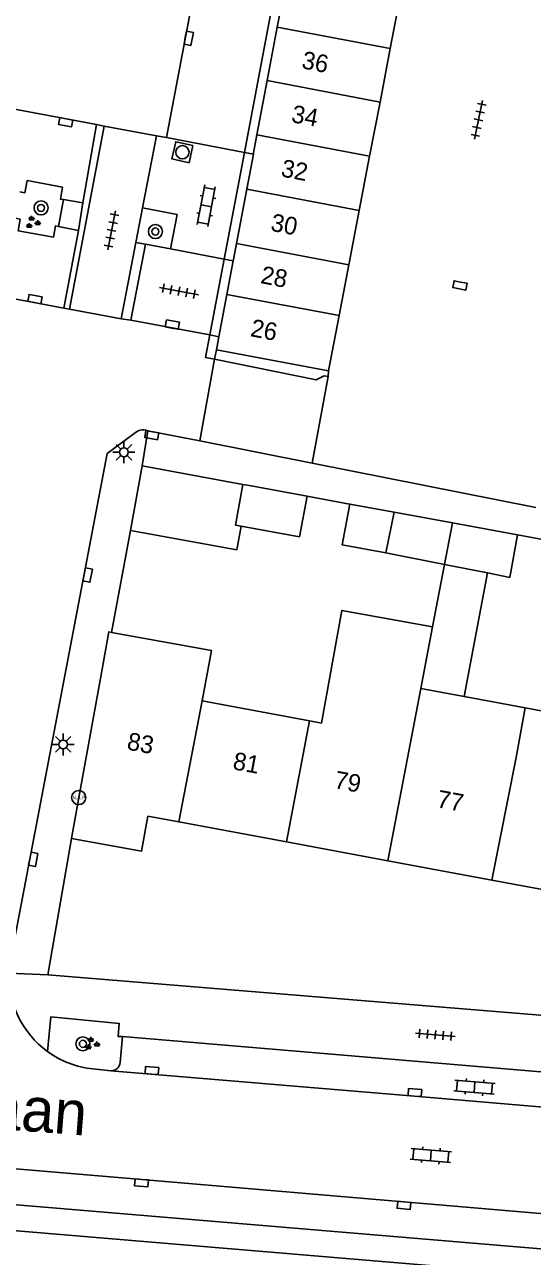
# Model space of a CAD drawing. Extents: x 131000 to 133014, y 396499 to 399001.
# Drawn here: x 131372.8 to 131401.6, y 397176.8 to 397246.7 of the extents above; entities that cross this region are included whole.
import ezdxf

# ---------------------------------------------------------------- set-up
doc = ezdxf.new("R2010")
doc.units = 0
for name, color, linetype in [('gg-afsc-erfafscheiding', 7, 'Continuous'), ('gg-afsc-muur', 7, 'Continuous'), ('gg-anno-huisnummerreeks BGT', 7, 'Continuous'), ('gg-anno-openbare ruimte label', 7, 'Continuous'), ('gg-bbg-bijgebouw', 7, 'Continuous'), ('gg-bbg-gedigitaliseerde bebouwing', 7, 'Continuous'), ('gg-bbg-gedigitaliseerde bijgebouw', 7, 'Continuous'), ('gg-bbg-hoofdgebouw', 7, 'Continuous'), ('gg-bbg-luifel en loopbrug', 7, 'Continuous'), ('gg-bbg-tussenscheiding', 7, 'Continuous'), ('gg-knt-verharding', 7, 'Continuous'), ('gg-knt-verharding nz', 7, 'Continuous'), ('gt-grn-vlakafsluiter', 7, 'Continuous'), ('gt-grn-weggrens', 7, 'Continuous'), ('gt-symb-boom', 7, 'Continuous'), ('gt-symb-groenvak', 7, 'Continuous'), ('gt-symb-hoogtemerk', 7, 'Continuous'), ('gt-symb-klinker verharding', 7, 'Continuous'), ('gt-symb-kolk', 7, 'Continuous'), ('gt-symb-lichtmast', 7, 'Continuous'), ('gt-symb-rioolschacht', 7, 'Continuous'), ('gt-symb-tegel verharding', 7, 'Continuous')]:
    doc.layers.add(name, color=color, linetype=linetype)

# ---------------------------------------------------------------- blocks, each defined once
blk = doc.blocks.new('gt0-KOLK')
at = {"layer": 'gt-symb-kolk'}
blk.add_lwpolyline([(0, 0), (0.375, 0), (0.375, 0.4), (-0.375, 0.4), (-0.375, 0), (0, 0)], dxfattribs=at)
blk = doc.blocks.new('gt0-TEG1')
at = {"layer": 'gt-symb-tegel verharding'}
for p, q in [((-1.125, 0), (1.125, 0)), ((-0.9, -0.25), (-0.9, 0.25)), ((-0.45, -0.25), (-0.45, 0.25)), ((0, -0.25), (0, 0.25)), ((0.45, -0.25), (0.45, 0.25)), ((0.9, -0.25), (0.9, 0.25))]:
    blk.add_line(p, q, dxfattribs=at)
blk = doc.blocks.new('gt0-RS')
at = {"layer": 'gt-symb-rioolschacht'}
blk.add_lwpolyline([(-0.5, -0.5), (0.5, -0.5), (0.5, 0.5), (-0.5, 0.5)], close=True, dxfattribs=at)
blk.add_circle((0, 0), 0.375, dxfattribs=at)
blk = doc.blocks.new('gt0-BOOM')
at = {"layer": 'gt-symb-boom'}
for radius in [0.4, 0.2]:
    blk.add_circle((0, 0), radius, dxfattribs=at)
blk = doc.blocks.new('gt0-KL1')
at = {"layer": 'gt-symb-klinker verharding'}
for p, q in [((-1.15, 0.3), (1.15, 0.3)), ((-1, -0.3), (-1, 0.3)), ((-0.5, 0.3), (-0.5, 0.45)), ((0, -0.3), (0, 0.3)), ((0.5, 0.3), (0.5, 0.45)), ((1, -0.3), (1, 0.3)), ((-1.15, -0.3), (1.15, -0.3)), ((-0.5, -0.45), (-0.5, -0.3)), ((0.5, -0.45), (0.5, -0.3))]:
    blk.add_line(p, q, dxfattribs=at)
blk = doc.blocks.new('gt0-HMERK')
at = {"layer": 'gt-symb-hoogtemerk'}
blk.add_circle((0, 0), 0.4, dxfattribs=at)
blk.add_text('N.A.P', height=0.2, dxfattribs=at).set_placement((-0.354, -0.1))
blk = doc.blocks.new('gt0-GRVAK')
at = {"layer": 'gt-symb-groenvak'}
for p, q in [((-0.11, 0.189), (-0.228, 0.24)), ((-0.182, 0.153), (0.088, 0.153)), ((-0.091, 0.211), (-0.156, 0.322)), ((-0.047, 0.214), (-0.047, 0.393)), ((-0.004, 0.211), (0.061, 0.322)), ((0.015, 0.189), (0.133, 0.24)), ((0.262, -0.052), (0.197, 0.059)), ((0.305, -0.049), (0.305, 0.13)), ((0.349, -0.052), (0.414, 0.059)), ((-0.245, -0.228), (-0.363, -0.177)), ((-0.318, -0.264), (-0.047, -0.264)), ((-0.226, -0.206), (-0.291, -0.095)), ((-0.183, -0.203), (-0.183, -0.024)), ((-0.139, -0.206), (-0.074, -0.095)), ((-0.12, -0.228), (-0.002, -0.177)), ((0.243, -0.074), (0.125, -0.023)), ((0.17, -0.11), (0.441, -0.11)), ((0.368, -0.074), (0.486, -0.023))]:
    blk.add_line(p, q, dxfattribs=at)
blk = doc.blocks.new('gt0-LMAST')
at = {"layer": 'gt-symb-lichtmast'}
for p, q in [((-0.182, 0.173), (-0.447, 0.438)), ((-0.005, 0.246), (-0.005, 0.621)), ((0.172, 0.173), (0.437, 0.438)), ((-0.255, -0.004), (-0.63, -0.004)), ((-0.182, -0.181), (-0.447, -0.446)), ((-0.005, -0.254), (-0.005, -0.629)), ((0.437, -0.446), (0.172, -0.181)), ((0.245, -0.004), (0.62, -0.004))]:
    blk.add_line(p, q, dxfattribs=at)
blk.add_circle((-0.005, -0.004), 0.25, dxfattribs=at)

msp = doc.modelspace()

# ---------------------------------------------------------------- linework, layer by layer
at = {"layer": 'gg-afsc-erfafscheiding'}
msp.add_line((131400.776, 397217.764), (131405.563, 397216.865), dxfattribs=at)
at = {"layer": 'gg-afsc-muur'}
msp.add_line((131378.8, 397218.02), (131377.72, 397212.226), dxfattribs=at)
msp.add_lwpolyline([(131388.824, 397219.956), (131391.235, 397219.512), (131391.243, 397219.511)], dxfattribs=at)
at = {"layer": 'gg-bbg-bijgebouw'}
for p, q in [((131387.709, 397249.616), (131387.134, 397246.58)), ((131393.545, 397245.362), (131394.126, 397248.397)), ((131387.134, 397246.58), (131386.562, 397243.555)), ((131392.966, 397242.332), (131393.545, 397245.362)), ((131386.562, 397243.555), (131385.98, 397240.473)), ((131392.966, 397242.332), (131392.376, 397239.25)), ((131385.787, 397239.451), (131385.98, 397240.473)), ((131385.397, 397237.391), (131385.774, 397239.38)), ((131385.774, 397239.38), (131385.787, 397239.451)), ((131392.376, 397239.25), (131391.787, 397236.169)), ((131385.397, 397237.391), (131384.814, 397234.308)), ((131391.787, 397236.169), (131391.198, 397233.089)), ((131384.814, 397234.308), (131384.661, 397233.497)), ((131384.627, 397233.319), (131384.266, 397231.408)), ((131384.661, 397233.497), (131384.627, 397233.319)), ((131391.198, 397233.089), (131390.648, 397230.216)), ((131384.266, 397231.408), (131383.813, 397229.013)), ((131390.648, 397230.216), (131390.046, 397227.067)), ((131383.813, 397229.013), (131383.673, 397228.271)), ((131390.046, 397227.067), (131383.673, 397228.271)), ((131378.8, 397218.02), (131379.47, 397221.68)), ((131379.47, 397221.68), (131385.184, 397220.627)), ((131385.184, 397220.627), (131385.45, 397220.578)), ((131385.45, 397220.578), (131388.824, 397219.956)), ((131393.761, 397219.051), (131397.089, 397218.44)), ((131385.078, 397218.262), (131384.83, 397216.91)), ((131397.089, 397218.44), (131400.776, 397217.764)), ((131384.83, 397216.91), (131378.8, 397218.02))]:
    msp.add_line(p, q, dxfattribs=at)
at = {"layer": 'gg-bbg-gedigitaliseerde bebouwing'}
for p, q in [((131395.95, 397212.536), (131395.283, 397209.045)), ((131395.283, 397209.045), (131397.747, 397208.585)), ((131397.747, 397208.585), (131401.2, 397207.94)), ((131382.862, 397208.335), (131388.967, 397207.205)), ((131388.967, 397207.205), (131389.641, 397207.08))]:
    msp.add_line(p, q, dxfattribs=at)
for points in [[(131389.641, 397207.08), (131390.805, 397213.472), (131395.95, 397212.536)], [(131377.72, 397212.226), (131383.393, 397211.203), (131382.862, 397208.335)], [(131401.2, 397207.94), (131407.153, 397206.832), (131407.033, 397206.197)]]:
    msp.add_lwpolyline(points, dxfattribs=at)
at = {"layer": 'gg-bbg-gedigitaliseerde bijgebouw'}
for p, q in [((131388.824, 397219.956), (131388.399, 397217.65)), ((131393.304, 397216.746), (131393.761, 397219.051)), ((131388.399, 397217.65), (131385.078, 397218.262)), ((131400.334, 397215.351), (131400.776, 397217.764)), ((131393.304, 397216.746), (131396.635, 397216.085)), ((131396.635, 397216.085), (131399.065, 397215.603)), ((131399.065, 397215.603), (131400.334, 397215.351))]:
    msp.add_line(p, q, dxfattribs=at)
at = {"layer": 'gg-bbg-hoofdgebouw'}
for p, q in [((131377.05, 397209.41), (131375.8, 397202.54)), ((131375.45, 397200.533), (131375.8, 397202.54)), ((131379.791, 397201.797), (131381.549, 397201.47)), ((131381.549, 397201.47), (131387.647, 397200.335)), ((131387.647, 397200.335), (131393.414, 397199.261)), ((131393.414, 397199.261), (131399.31, 397198.164)), ((131399.31, 397198.164), (131405.161, 397197.075))]:
    msp.add_line(p, q, dxfattribs=at)
for points in [[(131377.05, 397209.41), (131377.563, 397212.254), (131377.72, 397212.226)], [(131375.45, 397200.533), (131379.429, 397199.808), (131379.791, 397201.797)]]:
    msp.add_lwpolyline(points, dxfattribs=at)
at = {"layer": 'gg-bbg-luifel en loopbrug'}
for p, q in [((131391.243, 397219.511), (131393.761, 397219.051)), ((131395.95, 397212.536), (131396.635, 397216.085)), ((131397.747, 397208.585), (131399.065, 397215.603))]:
    msp.add_line(p, q, dxfattribs=at)
msp.add_lwpolyline([(131393.304, 397216.746), (131390.81, 397217.206), (131391.243, 397219.511)], dxfattribs=at)
at = {"layer": 'gg-bbg-tussenscheiding'}
for p, q in [((131393.545, 397245.362), (131387.134, 397246.58)), ((131392.966, 397242.332), (131386.562, 397243.555)), ((131392.376, 397239.25), (131385.98, 397240.473)), ((131391.787, 397236.169), (131385.397, 397237.391)), ((131391.198, 397233.089), (131384.814, 397234.308)), ((131384.266, 397231.408), (131390.648, 397230.216)), ((131397.089, 397218.44), (131396.635, 397216.085)), ((131395.283, 397209.045), (131393.414, 397199.261)), ((131382.862, 397208.335), (131381.549, 397201.47)), ((131400.672, 397205.024), (131401.2, 397207.94)), ((131388.967, 397207.205), (131387.647, 397200.335)), ((131400.672, 397205.024), (131399.31, 397198.164))]:
    msp.add_line(p, q, dxfattribs=at)
msp.add_lwpolyline([(131385.184, 397220.627), (131384.76, 397218.321), (131385.078, 397218.262)], dxfattribs=at)
at = {"layer": 'gg-knt-verharding'}
for p, q in [((131388.706, 397257.593), (131385.268, 397239.476)), ((131377.3, 397240.97), (131375.33, 397230.57)), ((131376.863, 397241.052), (131376.1, 397236.601)), ((131376.863, 397241.052), (131377.3, 397240.97)), ((131377.3, 397240.97), (131380.28, 397240.42)), ((131379.485, 397236.328), (131380.28, 397240.42)), ((131380.28, 397240.42), (131380.839, 397240.314)), ((131380.839, 397240.314), (131385.268, 397239.476)), ((131385.268, 397239.476), (131384.119, 397233.415)), ((131374.717, 397235.261), (131374.985, 397236.797)), ((131376.1, 397236.601), (131374.985, 397236.797)), ((131376.1, 397236.601), (131375.852, 397235.044)), ((131379.103, 397234.365), (131379.485, 397236.328)), ((131379.485, 397236.328), (131381.45, 397235.956)), ((131381.068, 397233.993), (131381.45, 397235.956)), ((131375.852, 397235.044), (131374.717, 397235.261)), ((131375.004, 397230.632), (131375.852, 397235.044)), ((131378.26, 397230.03), (131379.103, 397234.365)), ((131379.103, 397234.365), (131379.641, 397234.263)), ((131378.808, 397229.945), (131379.641, 397234.263)), ((131379.641, 397234.263), (131381.068, 397233.993)), ((131381.068, 397233.993), (131384.119, 397233.415)), ((131384.119, 397233.415), (131383.302, 397229.114)), ((131375.33, 397230.57), (131375.004, 397230.632)), ((131375.33, 397230.57), (131378.26, 397230.03)), ((131378.808, 397229.945), (131378.26, 397230.03)), ((131383.302, 397229.114), (131383.059, 397227.831)), ((131383.813, 397229.013), (131383.302, 397229.114)), ((131383.673, 397228.271), (131383.575, 397227.727)), ((131383.059, 397227.831), (131383.575, 397227.727)), ((131389.12, 397221.832), (131390.014, 397226.76)), ((131379.78, 397223.67), (131382.74, 397223.11)), ((131382.74, 397223.11), (131389.12, 397221.832)), ((131401.812, 397219.32), (131389.12, 397221.832)), ((131374.1, 397192.8), (131375.45, 397200.533)), ((131417.35, 397189.24), (131374.1, 397192.8)), ((131378.353, 397189.294), (131378.215, 397187.815)), ((131416.864, 397186.035), (131378.353, 397189.294)), ((131377.674, 397187.344), (131376.662, 397187.449)), ((131336.881, 397182.701), (131428.001, 397175.07))]:
    msp.add_line(p, q, dxfattribs=at)
for points in [[(131374.985, 397236.797), (131374.82, 397236.826), (131374.944, 397237.493), (131372.934, 397237.884), (131372.806, 397237.18), (131372.513, 397237.231)], [(131372.25, 397235.733), (131372.533, 397235.679), (131372.414, 397235.026), (131374.419, 397234.662), (131374.536, 397235.296), (131374.717, 397235.261)], [(131390.014, 397226.76), (131389.799, 397226.794), (131389.337, 397226.558), (131383.575, 397227.727)], [(131371.979, 397193.602), (131377.48, 397222.38), (131379, 397223.51)], [(131378.353, 397189.294), (131378.104, 397189.291), (131378.156, 397190.029), (131374.27, 397190.401), (131374.083, 397188.44)], [(131335.719, 397180.159), (131335.851, 397180.612), (131335.985, 397180.574), (131336.055, 397181.305), (131428.207, 397173.565)]]:
    msp.add_lwpolyline(points, dxfattribs=at)
for centre, radius, start, end in [((131379.506, 397223.022), 0.703, 67.10902, 136.07533), ((131377.21, 397192.725), 5.304, 178.23579, 233.87997), ((131377.214, 397192.736), 5.315, 233.9167, 264.04401), ((131377.702, 397187.858), 0.515, 266.90883, 355.17748)]:
    msp.add_arc(centre, radius, start, end, dxfattribs=at)
at = {"layer": 'gg-knt-verharding nz'}
for p, q in [((131380.839, 397240.314), (131384.264, 397258.431)), ((131370.26, 397242.293), (131376.863, 397241.052)), ((131375.004, 397230.632), (131368.368, 397231.887)), ((131378.808, 397229.945), (131383.302, 397229.114)), ((131383.575, 397227.727), (131382.74, 397223.11))]:
    msp.add_line(p, q, dxfattribs=at)
for points in [[(131417.209, 397184.025), (131413.778, 397184.305), (131394.929, 397185.911), (131377.674, 397187.344)], [(131336.355, 397184.752), (131338.015, 397184.631), (131339.957, 397184.459), (131356.374, 397183.115), (131379.442, 397181.182), (131413.171, 397178.306), (131428.671, 397177.01)]]:
    msp.add_lwpolyline(points, dxfattribs=at)
at = {"layer": 'gt-grn-vlakafsluiter'}
msp.add_line((131390.046, 397227.067), (131390.014, 397226.76), dxfattribs=at)
at = {"layer": 'gt-grn-weggrens'}
for p, q in [((131385.268, 397239.476), (131385.774, 397239.38)), ((131384.119, 397233.415), (131384.627, 397233.319)), ((131379.78, 397223.67), (131379.47, 397221.68)), ((131374.1, 397192.8), (131371.908, 397192.888))]:
    msp.add_line(p, q, dxfattribs=at)

# ---------------------------------------------------------------- block references
at = {"layer": 'gt-symb-boom'}
for p in [(131373.72, 397236.321), (131380.211, 397234.982), (131376.094, 397188.875)]:
    msp.add_blockref('gt0-BOOM', p, dxfattribs=at)
at = {"layer": 'gt-symb-groenvak'}
for p in [(131373.229, 397235.487), (131376.59, 397188.879)]:
    msp.add_blockref('gt0-GRVAK', p, dxfattribs=at)
at = {"layer": 'gt-symb-hoogtemerk'}
msp.add_blockref('gt0-HMERK', (131375.857, 397202.855), dxfattribs=at)
at = {"layer": 'gt-symb-klinker verharding'}
for p, rotation in [((131383.102, 397236.445), 79.2183832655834), ((131398.332, 397186.417), -4.701808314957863), ((131395.849, 397182.541), 175.29819168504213)]:
    msp.add_blockref('gt0-KL1', p, dxfattribs=dict(at, rotation=rotation))
at = {"layer": 'gt-symb-kolk'}
for p, rotation in [((131381.911, 397245.988), -100.89418298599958), ((131375.152, 397241.376), 169.5669752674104), ((131397.542, 397232.116), 168.5215179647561), ((131373.333, 397230.948), -11.130111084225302), ((131381.141, 397229.503), -10.36632260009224), ((131380.044, 397223.62), 169.56697526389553), ((131376.168, 397215.515), -100.89418298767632), ((131373.082, 397199.379), -100.83791044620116), ((131380, 397187.157), -4.758885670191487), ((131394.929, 397185.911), -4.8778808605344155), ((131379.442, 397181.182), 175.17923392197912), ((131394.343, 397179.905), 175.1221191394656)]:
    msp.add_blockref('gt0-KOLK', p, dxfattribs=dict(at, rotation=rotation))
at = {"layer": 'gt-symb-lichtmast'}
for p in [(131378.428, 397222.455), (131374.98, 397205.873)]:
    msp.add_blockref('gt0-LMAST', p, dxfattribs=at)
at = {"layer": 'gt-symb-rioolschacht', "rotation": 167.11702052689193}
msp.add_blockref('gt0-RS', (131381.746, 397239.481), dxfattribs=at)
at = {"layer": 'gt-symb-tegel verharding'}
for p, rotation in [((131398.561, 397241.323), -101.71452521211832), ((131377.723, 397235.051), 78.9933358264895), ((131381.545, 397231.596), -10.545734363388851), ((131396.106, 397189.385), -4.701808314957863)]:
    msp.add_blockref('gt0-TEG1', p, dxfattribs=dict(at, rotation=rotation))

# ---------------------------------------------------------------- texts
at = {"layer": 'gg-anno-huisnummerreeks BGT'}
for s, rotation, p in [('36', 349.2, (131388.47, 397244.253)), ('34', 349.2, (131387.885, 397241.198)), ('32', 349.2, (131387.296, 397238.116)), ('30', 349.2, (131386.707, 397235.035)), ('28', 349.2, (131386.137, 397232.06)), ('26', 349.2, (131385.561, 397229.048)), ('83', 349.5, (131378.551, 397205.588)), ('81', 349.5, (131384.561, 397204.469)), ('79', 349.5, (131390.318, 397203.397)), ('77', 349.5, (131396.144, 397202.312))]:
    msp.add_text(s, height=1, rotation=rotation, dxfattribs=at).set_placement(p)
at = {"layer": 'gg-anno-openbare ruimte label'}
msp.add_text('Professor Verbernelaan', height=2.5, rotation=355.5, dxfattribs=at).set_placement((131341.04, 397186.433))

doc.saveas('drawing.dxf')
